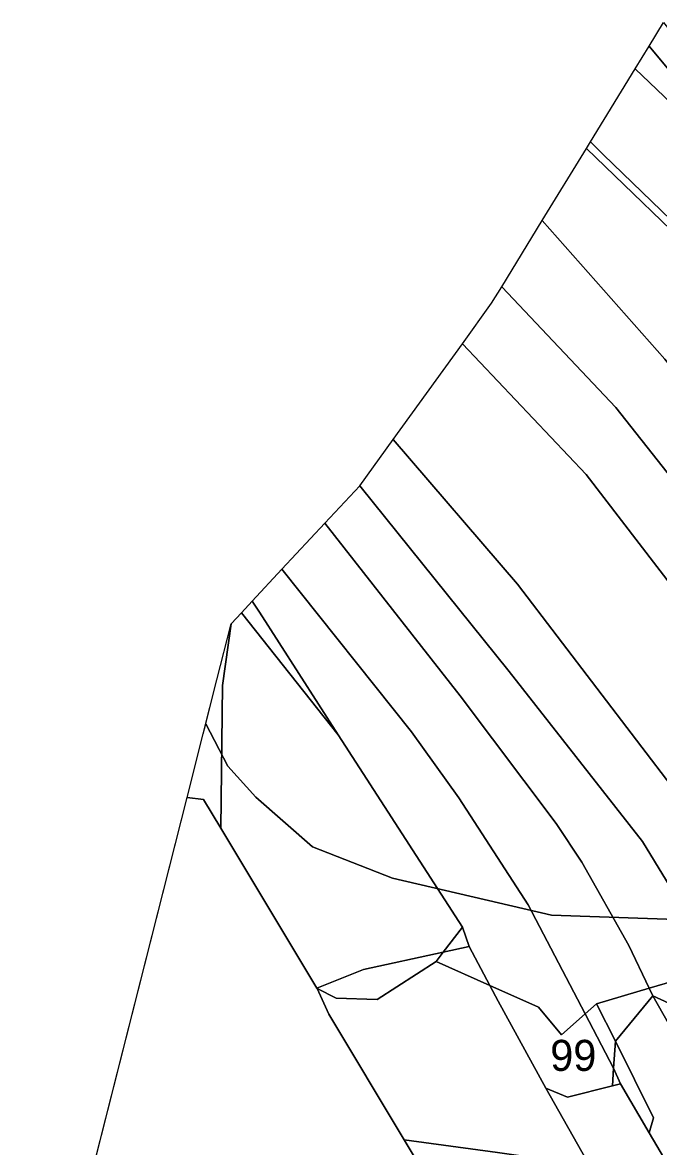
# Model space of a CAD drawing. Extents: x -537068 to -534056, y -1176840 to -1172401.
# Drawn here: x -537003.4 to -536900.9, y -1173732.3 to -1173551.2 of the extents above; entities that cross this region are included whole.
import ezdxf

# ---------------------------------------------------------------- set-up
doc = ezdxf.new("R2010")
doc.units = 0
for name, color, linetype in [('95580013', 7, 'Continuous'), ('95610013', 7, 'Continuous'), ('95640013', 7, 'Continuous'), ('95660013', 7, 'Continuous')]:
    doc.layers.add(name, color=color, linetype=linetype)

msp = doc.modelspace()

# ---------------------------------------------------------------- linework, layer by layer
at = {"layer": '95580013'}
for points in [[(-536909.76, -1173572.5), (-536892.69, -1173589.02), (-536877.28, -1173607.47), (-536892.94, -1173590.39), (-536912.55, -1173571.48), (-536911.89, -1173570.39)], [(-536899.91, -1173605.44), (-536919.66, -1173583.1), (-536912.55, -1173571.48), (-536892.94, -1173590.39), (-536877.28, -1173607.47), (-536871.63, -1173614.24), (-536844.37, -1173648.47), (-536828.27, -1173668.04), (-536795.97, -1173719.79), (-536807.52, -1173720.67), (-536814.12, -1173716.89), (-536816.82, -1173712.14), (-536842.19, -1173678.03), (-536858.93, -1173655.49), (-536879.33, -1173630.2)], [(-536814.12, -1173716.89), (-536816.89, -1173715.3), (-536830.12, -1173718.3), (-536841.16, -1173700.73), (-536860.73, -1173673.09), (-536890.44, -1173635.15), (-536907.81, -1173613.19), (-536926.19, -1173593.77), (-536919.66, -1173583.1), (-536899.91, -1173605.44), (-536879.33, -1173630.2), (-536858.93, -1173655.49), (-536842.19, -1173678.03), (-536816.82, -1173712.14)], [(-536926.19, -1173593.77), (-536907.81, -1173613.19), (-536890.44, -1173635.15), (-536860.73, -1173673.09), (-536841.16, -1173700.73), (-536830.12, -1173718.3), (-536837.38, -1173719.95), (-536839.52, -1173717.94), (-536846.34, -1173707.23), (-536852.43, -1173705.78), (-536875.56, -1173672.15), (-536912.59, -1173624), (-536932.52, -1173602.93), (-536927.81, -1173596.41)], [(-536874.31, -1173706.54), (-536880.69, -1173702.42), (-536891.69, -1173683.55), (-536923.64, -1173641.65), (-536943.67, -1173618.35), (-536932.52, -1173602.93), (-536912.59, -1173624), (-536875.56, -1173672.15), (-536852.43, -1173705.78), (-536853.61, -1173704.66), (-536860.56, -1173711.34), (-536866.29, -1173709.34), (-536868.89, -1173708.43)], [(-536903.48, -1173683.1), (-536925, -1173655.75), (-536949.07, -1173625.83), (-536943.67, -1173618.35), (-536923.64, -1173641.65), (-536891.69, -1173683.55), (-536880.69, -1173702.42), (-536882.88, -1173701.01), (-536891.59, -1173703.57), (-536895.75, -1173695.79)], [(-536905.72, -1173699.87), (-536913.26, -1173686.46), (-536917.43, -1173680.2), (-536932.9, -1173659.68), (-536954.69, -1173631.85), (-536949.07, -1173625.83), (-536925, -1173655.75), (-536903.48, -1173683.1), (-536895.75, -1173695.79), (-536891.59, -1173703.57), (-536902.41, -1173706.75)], [(-536932.9, -1173659.68), (-536917.43, -1173680.2), (-536913.26, -1173686.46), (-536905.72, -1173699.87), (-536902.41, -1173706.75), (-536910.9, -1173709.24), (-536912.74, -1173710.88), (-536921.92, -1173693.32), (-536933.1, -1173676.08), (-536940.74, -1173665.45), (-536961.6, -1173639.27), (-536954.69, -1173631.85)], [(-536912.74, -1173710.88), (-536916.56, -1173714.28), (-536920.26, -1173709.8), (-536928.11, -1173706.3), (-536931.45, -1173700.04), (-536932.53, -1173696.93), (-536952.52, -1173665.92), (-536965.23, -1173646.2), (-536966.39, -1173644.41), (-536961.6, -1173639.27), (-536940.74, -1173665.45), (-536933.1, -1173676.08), (-536921.92, -1173693.32)], [(-536931.45, -1173700.04), (-536935.6, -1173700.95), (-536932.53, -1173696.93)]]:
    msp.add_lwpolyline(points, close=True, dxfattribs=at)
at = {"layer": '95610013'}
for points in [[(-536902.45, -1173554.98), (-536879.11, -1173583.06), (-536904.71, -1173558.67)], [(-536828.27, -1173668.04), (-536844.37, -1173648.47), (-536871.63, -1173614.24), (-536877.28, -1173607.47), (-536892.69, -1173589.02), (-536909.76, -1173572.5), (-536911.89, -1173570.39), (-536904.71, -1173558.67), (-536879.11, -1173583.06), (-536873.49, -1173589.79), (-536845.07, -1173624.31), (-536815.72, -1173662.39), (-536800.26, -1173683.76), (-536777.6, -1173723.61), (-536775.96, -1173726.62), (-536790.16, -1173726.67), (-536796.42, -1173715.43), (-536808.99, -1173696.74)], [(-536966.39, -1173644.41), (-536965.23, -1173646.2), (-536952.52, -1173665.92), (-536968.14, -1173646.29)], [(-536952.52, -1173665.92), (-536932.53, -1173696.93), (-536935.6, -1173700.95), (-536948.45, -1173703.75), (-536955.96, -1173706.74), (-536971.45, -1173680.95), (-536971.2, -1173658.01), (-536969.8, -1173648.07), (-536968.14, -1173646.29)], [(-536895.98, -1173710.67), (-536901.82, -1173707.97), (-536902.41, -1173706.75), (-536891.59, -1173703.57), (-536889.05, -1173708.31)], [(-536907.87, -1173715.29), (-536910.9, -1173709.24), (-536902.41, -1173706.75), (-536901.82, -1173707.97)], [(-536907.87, -1173715.29), (-536901.82, -1173707.97), (-536883.53, -1173740.28), (-536876.38, -1173751.98), (-536890.58, -1173750.19), (-536902.42, -1173730.04), (-536901.71, -1173727.62)], [(-536865.19, -1173750.93), (-536869.68, -1173752.83), (-536876.38, -1173751.98), (-536883.53, -1173740.28), (-536901.82, -1173707.97), (-536895.98, -1173710.67), (-536889.05, -1173708.31), (-536876.71, -1173731.38)]]:
    msp.add_lwpolyline(points, close=True, dxfattribs=at)
at = {"layer": '95640013'}
for points in [[(-536814.43, -1173660.95), (-536846.42, -1173619.82), (-536874.64, -1173587.31), (-536879.11, -1173583.06), (-536902.45, -1173554.98), (-536900.13, -1173551.19), (-536870.03, -1173588.72), (-536796.82, -1173679.68), (-536773.89, -1173720.12), (-536760.44, -1173742.57), (-536762.85, -1173744.9), (-536768.25, -1173734.85), (-536776.21, -1173720.04), (-536793.79, -1173690.29), (-536803.42, -1173675.57)], [(-536974.22, -1173676.33), (-536976.89, -1173676.04), (-536974.28, -1173665.76), (-536972.08, -1173657.08), (-536969.8, -1173648.07), (-536971.2, -1173658.01), (-536971.45, -1173680.95)], [(-536957.43, -1173782.63), (-536966.12, -1173780.28), (-536969.3, -1173776.73), (-536970.56, -1173779.09), (-536984.29, -1173775.39), (-537003.41, -1173770.23), (-536998.3, -1173760.8), (-536996.52, -1173753.5), (-536976.89, -1173676.04), (-536974.22, -1173676.33), (-536971.45, -1173680.95), (-536955.96, -1173706.74), (-536955.94, -1173706.79), (-536954.05, -1173710.95), (-536941.89, -1173731.15), (-536922.12, -1173764.02), (-536917.89, -1173771.05), (-536917.12, -1173772.33), (-536910.62, -1173777.35), (-536914.09, -1173778.66), (-536929.59, -1173784.53), (-536931.53, -1173784.4), (-536955.97, -1173782.73)], [(-536936.75, -1173702.45), (-536946.27, -1173708.58), (-536952.84, -1173708.34), (-536955.94, -1173706.79), (-536955.96, -1173706.74), (-536948.45, -1173703.75), (-536935.6, -1173700.95)], [(-536936.75, -1173702.45), (-536935.6, -1173700.95), (-536931.45, -1173700.04), (-536928.11, -1173706.3)], [(-536919.09, -1173722.85), (-536911.88, -1173735.6), (-536914.76, -1173734.95), (-536926.88, -1173733.2), (-536941.89, -1173731.15), (-536954.05, -1173710.95), (-536955.94, -1173706.79), (-536952.84, -1173708.34), (-536946.27, -1173708.58), (-536936.75, -1173702.45), (-536928.11, -1173706.3), (-536926.74, -1173708.86)], [(-536908.16, -1173719.65), (-536908.35, -1173722.48), (-536915.59, -1173724.28), (-536919.09, -1173722.85), (-536926.74, -1173708.86), (-536928.11, -1173706.3), (-536920.26, -1173709.8), (-536916.56, -1173714.28), (-536912.74, -1173710.88)], [(-536912.74, -1173710.88), (-536910.9, -1173709.24), (-536907.87, -1173715.29), (-536908.16, -1173719.65)], [(-536907.87, -1173715.29), (-536901.71, -1173727.62), (-536902.42, -1173730.04), (-536907.05, -1173722.16), (-536908.16, -1173719.65)], [(-536907.05, -1173722.16), (-536908.35, -1173722.48), (-536908.16, -1173719.65)], [(-536888.41, -1173774.93), (-536892.62, -1173769.09), (-536894.03, -1173767.14), (-536904.38, -1173748.85), (-536911.88, -1173735.6), (-536919.09, -1173722.85), (-536915.59, -1173724.28), (-536908.35, -1173722.48), (-536907.05, -1173722.16), (-536902.42, -1173730.04), (-536890.58, -1173750.19), (-536884.31, -1173760.87), (-536876.37, -1173772.2), (-536874.65, -1173774.65), (-536878.89, -1173775.4)], [(-536922.12, -1173764.02), (-536941.89, -1173731.15), (-536926.88, -1173733.2), (-536914.76, -1173734.95), (-536911.88, -1173735.6), (-536904.38, -1173748.85), (-536905.17, -1173748.77), (-536917.53, -1173751.18), (-536917.94, -1173761.52)]]:
    msp.add_lwpolyline(points, close=True, dxfattribs=at)
at = {"layer": '95660013'}
for points in [[(-536888.81, -1173696), (-536918.19, -1173695), (-536943.81, -1173689), (-536956.69, -1173684), (-536965.81, -1173676), (-536970.31, -1173671), (-536973.87, -1173664.14), (-536972.08, -1173657.08), (-536969.8, -1173648.07), (-536968.14, -1173646.29), (-536966.39, -1173644.41), (-536961.6, -1173639.27), (-536954.69, -1173631.85), (-536949.07, -1173625.83), (-536943.67, -1173618.35), (-536932.52, -1173602.93), (-536927.81, -1173596.41), (-536926.19, -1173593.77), (-536919.66, -1173583.1), (-536912.55, -1173571.48), (-536911.89, -1173570.39), (-536904.71, -1173558.67), (-536902.45, -1173554.98), (-536900.13, -1173551.19)], [(-536994.61, -1173745.96), (-536976.89, -1173676.04), (-536974.28, -1173665.76), (-536973.87, -1173664.14), (-536970.31, -1173671), (-536965.81, -1173676), (-536956.69, -1173684), (-536943.81, -1173689), (-536918.19, -1173695), (-536888.81, -1173696), (-536874.81, -1173698), (-536859.37, -1173707), (-536852.81, -1173714), (-536842.62, -1173729), (-536838.81, -1173744)]]:
    msp.add_lwpolyline(points, dxfattribs=at)

# ---------------------------------------------------------------- texts
msp.add_text('99', height=5, rotation=0, dxfattribs=at).set_placement((-536918.37, -1173720.07))

doc.saveas('drawing.dxf')
